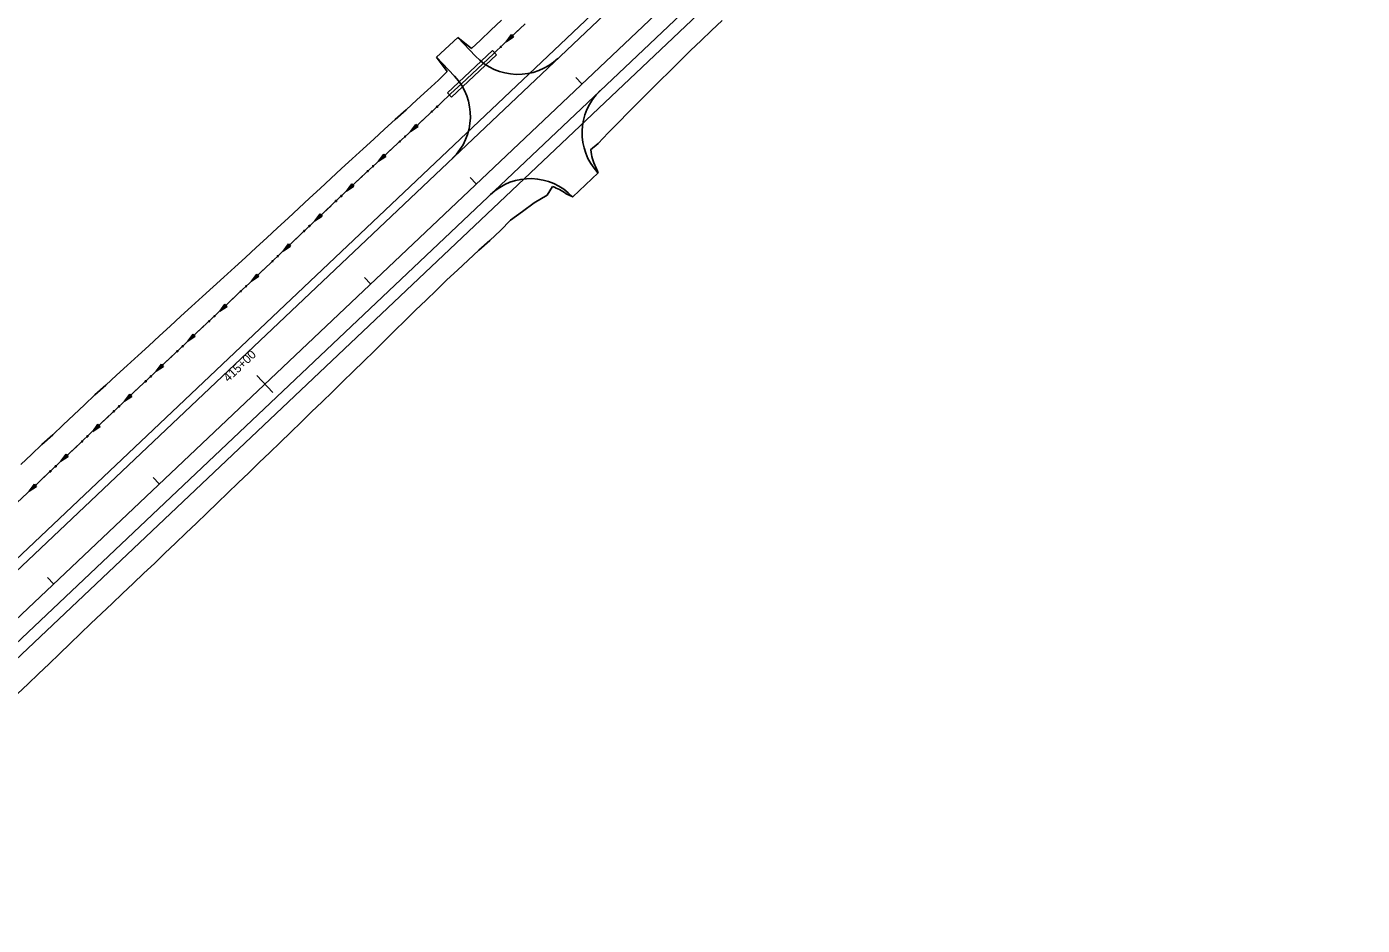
# Model space of a CAD drawing. Extents: x 1375694 to 1433473, y 1931050 to 1967991.
# Drawn here: x 1429493 to 1430411, y 1964028 to 1964646 of the extents above; entities that cross this region are included whole.
import ezdxf

# ---------------------------------------------------------------- set-up
doc = ezdxf.new("R2010")
doc.units = 0
for name, color, linetype in [('62', 7, 'Continuous'), ('R_Drainage', 7, 'Continuous'), ('R_Horz Alg', 7, 'Continuous'), ('R_Horz Alg Annot', 7, 'Continuous'), ('R_Proposed Const Limits', 7, 'Continuous'), ('R_Proposed Road', 7, 'Continuous')]:
    doc.layers.add(name, color=color, linetype=linetype)

msp = doc.modelspace()

# ---------------------------------------------------------------- linework, layer by layer
at = {"layer": '62'}
for p, q in [((1429826.28, 1964640.1), (1429822.66, 1964635.2)), ((1429822.66, 1964635.2), (1429827.74, 1964638.57)), ((1429827.74, 1964638.57), (1429826.28, 1964640.1)), ((1429760.63, 1964578.39), (1429756.95, 1964573.54)), ((1429756.95, 1964573.54), (1429762.07, 1964576.84)), ((1429762.07, 1964576.84), (1429760.63, 1964578.39)), ((1429738.59, 1964557.98), (1429734.9, 1964553.13)), ((1429734.9, 1964553.13), (1429740.03, 1964556.43)), ((1429740.03, 1964556.43), (1429738.59, 1964557.98)), ((1429716.61, 1964537.5), (1429712.97, 1964532.61)), ((1429718.06, 1964535.96), (1429716.61, 1964537.5)), ((1429712.97, 1964532.61), (1429718.06, 1964535.96)), ((1429694.75, 1964516.89), (1429691.11, 1964512)), ((1429691.11, 1964512), (1429696.2, 1964515.35)), ((1429696.2, 1964515.35), (1429694.75, 1964516.89)), ((1429672.95, 1964496.21), (1429669.34, 1964491.31)), ((1429669.34, 1964491.31), (1429674.41, 1964494.68)), ((1429674.41, 1964494.68), (1429672.95, 1964496.21)), ((1429651.2, 1964475.5), (1429647.58, 1964470.6)), ((1429647.58, 1964470.6), (1429652.66, 1964473.97)), ((1429652.66, 1964473.97), (1429651.2, 1964475.5)), ((1429629.37, 1964454.88), (1429625.73, 1964449.99)), ((1429630.82, 1964453.34), (1429629.37, 1964454.88)), ((1429625.73, 1964449.99), (1429630.82, 1964453.34)), ((1429607.52, 1964434.26), (1429603.88, 1964429.37)), ((1429603.88, 1964429.37), (1429608.97, 1964432.73)), ((1429608.97, 1964432.73), (1429607.52, 1964434.26)), ((1429585.7, 1964413.61), (1429582.08, 1964408.72)), ((1429582.08, 1964408.72), (1429587.16, 1964412.08)), ((1429587.16, 1964412.08), (1429585.7, 1964413.61)), ((1429563.89, 1964392.96), (1429560.26, 1964388.07)), ((1429560.26, 1964388.07), (1429565.35, 1964391.42)), ((1429565.35, 1964391.42), (1429563.89, 1964392.96)), ((1429542.07, 1964372.32), (1429538.44, 1964367.43)), ((1429543.52, 1964370.78), (1429542.07, 1964372.32)), ((1429538.44, 1964367.43), (1429543.52, 1964370.78)), ((1429520.22, 1964351.71), (1429516.58, 1964346.82)), ((1429516.58, 1964346.82), (1429521.67, 1964350.17)), ((1429521.67, 1964350.17), (1429520.22, 1964351.71)), ((1429498.35, 1964331.12), (1429494.71, 1964326.23)), ((1429494.71, 1964326.23), (1429499.8, 1964329.58)), ((1429499.8, 1964329.58), (1429498.35, 1964331.12))]:
    msp.add_line(p, q, dxfattribs=at)
for points in [[(1429486.33, 1964318.33), (1429493.6, 1964325.19), (1429500.88, 1964332.05), (1429508.17, 1964338.9), (1429515.45, 1964345.76), (1429522.73, 1964352.61), (1429530.01, 1964359.47), (1429537.28, 1964366.33), (1429544.54, 1964373.2), (1429551.81, 1964380.08), (1429559.07, 1964386.95), (1429566.34, 1964393.82), (1429573.6, 1964400.69), (1429580.86, 1964407.57), (1429588.12, 1964414.45), (1429595.38, 1964421.32), (1429602.64, 1964428.2), (1429609.91, 1964435.07), (1429617.18, 1964441.93), (1429624.46, 1964448.79), (1429631.74, 1964455.65), (1429639.01, 1964462.51), (1429646.29, 1964469.37), (1429653.54, 1964476.26), (1429660.78, 1964483.16), (1429668.02, 1964490.05), (1429675.26, 1964496.95), (1429682.5, 1964503.85), (1429689.76, 1964510.73), (1429697.04, 1964517.59), (1429704.31, 1964524.45), (1429711.59, 1964531.31), (1429718.86, 1964538.17), (1429726.15, 1964545.02), (1429733.48, 1964551.81), (1429740.82, 1964558.61), (1429748.16, 1964565.4), (1429755.5, 1964572.2), (1429762.83, 1964578.99), (1429770.13, 1964585.84), (1429777.42, 1964592.68), (1429784.71, 1964599.52), (1429792, 1964606.37), (1429799.29, 1964613.21), (1429806.59, 1964620.05), (1429813.88, 1964626.9), (1429821.15, 1964633.77), (1429828.4, 1964640.65), (1429835.65, 1964647.54)], [(1429833.53, 1964645.53), (1429828.4, 1964640.65), (1429822.66, 1964635.2)], [(1429767.92, 1964583.77), (1429762.83, 1964578.99), (1429756.95, 1964573.54)], [(1429767.95, 1964583.79), (1429767.92, 1964583.77)], [(1429745.91, 1964563.32), (1429740.82, 1964558.61), (1429734.9, 1964553.13)], [(1429745.94, 1964563.34), (1429745.91, 1964563.32)], [(1429723.89, 1964542.9), (1429718.86, 1964538.17), (1429712.97, 1964532.61)], [(1429723.91, 1964542.92), (1429723.89, 1964542.9)], [(1429702.03, 1964522.29), (1429697.04, 1964517.59), (1429691.11, 1964512)], [(1429702.05, 1964522.32), (1429702.03, 1964522.29)], [(1429680.2, 1964501.66), (1429675.26, 1964496.95), (1429669.34, 1964491.31)], [(1429680.23, 1964501.68), (1429680.2, 1964501.66)], [(1429658.45, 1964480.94), (1429653.54, 1964476.26), (1429647.58, 1964470.6)], [(1429658.48, 1964480.96), (1429658.45, 1964480.94)], [(1429636.64, 1964460.28), (1429631.74, 1964455.65), (1429625.73, 1964449.99)], [(1429636.67, 1964460.31), (1429636.64, 1964460.28)], [(1429614.79, 1964439.67), (1429609.91, 1964435.07), (1429603.88, 1964429.37)], [(1429614.82, 1964439.7), (1429614.79, 1964439.67)], [(1429592.97, 1964419.03), (1429588.12, 1964414.45), (1429582.08, 1964408.72)], [(1429592.99, 1964419.06), (1429592.97, 1964419.03)], [(1429571.16, 1964398.38), (1429566.34, 1964393.82), (1429560.26, 1964388.07)], [(1429571.19, 1964398.4), (1429571.16, 1964398.38)], [(1429549.34, 1964377.74), (1429544.54, 1964373.2), (1429538.44, 1964367.43)], [(1429549.36, 1964377.76), (1429549.34, 1964377.74)], [(1429527.5, 1964357.11), (1429522.73, 1964352.61), (1429516.58, 1964346.82)], [(1429527.53, 1964357.13), (1429527.5, 1964357.11)], [(1429505.63, 1964336.52), (1429500.88, 1964332.05), (1429494.71, 1964326.23)], [(1429505.66, 1964336.54), (1429505.63, 1964336.52)]]:
    msp.add_lwpolyline(points, dxfattribs=at)
for centre in [(1429819.05, 1964631.73), (1429771.6, 1964587.18), (1429775.26, 1964590.6), (1429749.62, 1964566.7), (1429753.3, 1964570.11), (1429727.58, 1964546.3), (1429731.26, 1964549.7), (1429709.35, 1964529.15), (1429705.71, 1964525.71), (1429683.87, 1964505.09), (1429687.5, 1964508.54), (1429662.11, 1964484.38), (1429665.74, 1964487.83), (1429640.32, 1964463.7), (1429643.97, 1964467.14), (1429622.11, 1964446.53), (1429618.47, 1964443.09), (1429596.64, 1964422.46), (1429600.27, 1964425.91), (1429574.83, 1964401.8), (1429578.47, 1964405.25), (1429553.01, 1964381.16), (1429556.65, 1964384.6), (1429534.82, 1964363.96), (1429531.18, 1964360.52), (1429509.31, 1964339.93), (1429512.96, 1964343.37)]:
    msp.add_circle(centre, 0.375, dxfattribs=at)
at = {"layer": 'R_Drainage'}
for p, q in [((1429813.32, 1964629.12), (1429782.43, 1964600.13)), ((1429816.06, 1964626.2), (1429813.32, 1964629.12)), ((1429785.17, 1964597.21), (1429816.06, 1964626.2)), ((1429782.43, 1964600.13), (1429785.17, 1964597.21))]:
    msp.add_line(p, q, dxfattribs=at)
at = {"layer": 'R_Horz Alg'}
msp.add_line((1429279.02, 1964042.46), (1430431.75, 1965133.47), dxfattribs=at)
at = {"layer": 'R_Horz Alg Annot'}
for points in [[(1429870.59, 1964610.61), (1429874.72, 1964606.26)], [(1429797.97, 1964541.88), (1429802.09, 1964537.52)], [(1429725.34, 1964473.14), (1429729.46, 1964468.78)], [(1429651.33, 1964405.85), (1429662.33, 1964394.23)], [(1429580.08, 1964335.66), (1429584.21, 1964331.3)], [(1429507.45, 1964266.92), (1429511.58, 1964262.56)]]:
    msp.add_lwpolyline(points, dxfattribs=at)
at = {"layer": 'R_Proposed Const Limits'}
for p, q in [((1429789.44, 1964638.17), (1429798.75, 1964630.51)), ((1429774.75, 1964624.59), (1429782.04, 1964614.71)), ((1429884.19, 1964549.02), (1429885.85, 1964545.04)), ((1429863.81, 1964530.78), (1429868.41, 1964528.55))]:
    msp.add_line(p, q, dxfattribs=at)
for points in [[(1429798.75, 1964630.51), (1429804.98, 1964636.3), (1429812.19, 1964643.23), (1429819.46, 1964650.1)], [(1429880.74, 1964560.84), (1429885.98, 1964565.26), (1429892.8, 1964572.6), (1429899.83, 1964579.72), (1429906.86, 1964586.84), (1429913.93, 1964593.92), (1429921.03, 1964600.97), (1429928.14, 1964608), (1429935.23, 1964615.06), (1429942.35, 1964622.09), (1429949.44, 1964629.14), (1429956.63, 1964636.09), (1429963.91, 1964642.95), (1429971.19, 1964649.81)], [(1429488.97, 1964344.64), (1429496.33, 1964351.4), (1429503.59, 1964358.28), (1429510.95, 1964365.06), (1429518.21, 1964371.93), (1429525.45, 1964378.83), (1429532.77, 1964385.64), (1429540.02, 1964392.53), (1429547.43, 1964399.25), (1429554.83, 1964405.98), (1429562.2, 1964412.74), (1429569.61, 1964419.46), (1429576.94, 1964426.27), (1429584.33, 1964433), (1429591.65, 1964439.81), (1429599.05, 1964446.54), (1429606.44, 1964453.28), (1429613.82, 1964460.03), (1429621.27, 1964466.71), (1429628.64, 1964473.47), (1429636.07, 1964480.16), (1429643.43, 1964486.93), (1429650.8, 1964493.7), (1429658.18, 1964500.45), (1429665.51, 1964507.25), (1429672.92, 1964513.97), (1429680.22, 1964520.81), (1429687.56, 1964527.6), (1429694.88, 1964534.41), (1429702.21, 1964541.22), (1429709.53, 1964548.03), (1429716.87, 1964554.82), (1429724.26, 1964561.56), (1429731.65, 1964568.3), (1429739.04, 1964575.04), (1429746.42, 1964581.79), (1429753.88, 1964588.45), (1429761.25, 1964595.22), (1429768.64, 1964601.95), (1429776.04, 1964608.69), (1429782.04, 1964614.71)], [(1429825.67, 1964512.6), (1429833.92, 1964518.44), (1429841.91, 1964524.54), (1429850.82, 1964529.67), (1429854.61, 1964535.64)], [(1429781.95, 1964471.52), (1429789.31, 1964478.29), (1429796.62, 1964485.11), (1429803.94, 1964491.92), (1429811.39, 1964498.6), (1429818.72, 1964505.4), (1429825.67, 1964512.6)], [(1429486.79, 1964186.92), (1429494.02, 1964193.82), (1429501.24, 1964200.74), (1429508.46, 1964207.66), (1429515.69, 1964214.57), (1429522.9, 1964221.5), (1429530.11, 1964228.43), (1429537.27, 1964235.41), (1429544.58, 1964242.24), (1429551.77, 1964249.18), (1429559.02, 1964256.08), (1429566.3, 1964262.93), (1429573.5, 1964269.87), (1429580.82, 1964276.69), (1429588.03, 1964283.62), (1429595.3, 1964290.48), (1429602.55, 1964297.37), (1429609.73, 1964304.33), (1429616.94, 1964311.26), (1429624.13, 1964318.21), (1429631.34, 1964325.14), (1429638.54, 1964332.09), (1429645.74, 1964339.02), (1429652.93, 1964345.97), (1429660.13, 1964352.91), (1429667.32, 1964359.86), (1429674.56, 1964366.76), (1429681.71, 1964373.76), (1429688.86, 1964380.74), (1429696.1, 1964387.64), (1429703.26, 1964394.63), (1429710.41, 1964401.62), (1429717.55, 1964408.62), (1429724.73, 1964415.58), (1429731.84, 1964422.62), (1429738.95, 1964429.66), (1429746.11, 1964436.65), (1429753.24, 1964443.65), (1429760.43, 1964450.6), (1429767.61, 1964457.57), (1429774.78, 1964464.54), (1429781.95, 1964471.52)]]:
    msp.add_lwpolyline(points, dxfattribs=at)
for centre, radius, start, end in [((1429921.02, 1964566.16), 40.62, 187.54, 204.95869), ((1429842.19, 1964500.99), 36.81, 54.01295, 70.268)]:
    msp.add_arc(centre, radius, start, end, dxfattribs=at)
at = {"layer": 'R_Proposed Road'}
for p, q in [((1429258.4, 1964064.25), (1430411.13, 1965155.26)), ((1429262.53, 1964059.89), (1430415.26, 1965150.9)), ((1429287.27, 1964033.74), (1430440, 1965124.75)), ((1429292.77, 1964027.93), (1430445.5, 1965118.94)), ((1429774.75, 1964624.59), (1429789.44, 1964638.17)), ((1429789.44, 1964638.17), (1429801.67, 1964625.24)), ((1429774.75, 1964624.59), (1429787.15, 1964611.5)), ((1429868.41, 1964528.55), (1429885.85, 1964545.04)), ((1429885.85, 1964545.04), (1429885.77, 1964545.12)), ((1429868.41, 1964528.55), (1429868.34, 1964528.62))]:
    msp.add_line(p, q, dxfattribs=at)
for centre, start, end in [((1429830.73, 1964652.74), 223.42441, 313.42441), ((1429758.1, 1964584), 313.42441, 43.42441), ((1429914.82, 1964572.61), 133.42441, 223.42441), ((1429839.29, 1964501.13), 43.42441, 133.42441)]:
    msp.add_arc(centre, 40, start, end, dxfattribs=at)

# ---------------------------------------------------------------- texts
at = {"layer": 'R_Horz Alg Annot'}
msp.add_text('415+00', height=6, rotation=43.42441, dxfattribs=at).set_placement((1429631.65, 1964400.98))

doc.saveas('drawing.dxf')
